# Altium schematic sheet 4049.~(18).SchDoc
size A4
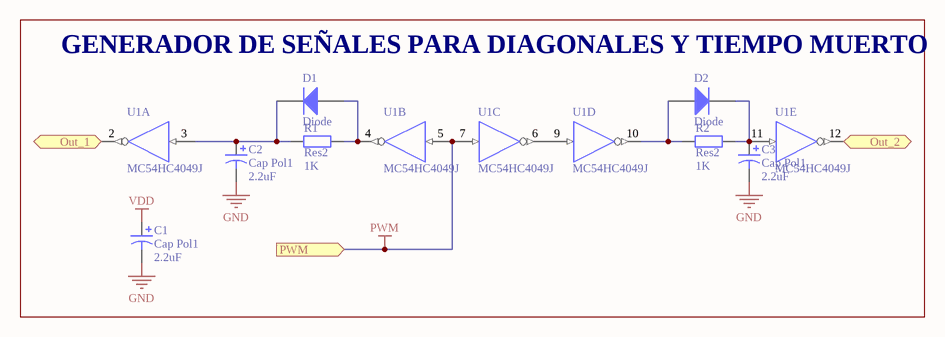
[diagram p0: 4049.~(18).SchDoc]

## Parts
C1  Cap Pol1  value 2.2uF  [CAPPR2.5-6.3X5]
C2  Cap Pol1  value 2.2uF  [CAPPR2.5-6.3X5]
C3  Cap Pol1  value 2.2uF  [CAPPR2.5-6.3X5]
D1  Diode  [DO-204AL]
D2  Diode  [DO-204AL]
R1  Res2  value 1K  [AXIAL-0.3]
R2  Res2  value 1K  [AXIAL-0.3]
U1  MC54HC4049J  [620-09]  (parts A,B,C,D,E of 6)

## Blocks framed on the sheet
GENERADOR DE SEÑALES PARA DIAGONALES Y TIEMPO MUERTO: C1-C3 D1 D2 R1 R2 U1

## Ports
Out_1 (out), Out_2 (out), PWM (in)

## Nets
GND: C1.2 C2.2 C3.2 U1.8(GND)
PWM: U1.5(A) U1.7(A) ; port PWM
VDD: C1.1 U1.1(VDD)
Out_1: U1.2(Y) ; port Out_1
Out_2: U1.12(Y) ; port Out_2
NetC2_1: C2.1 D1.2(K) R1.1 U1.3(A)
NetC3_1: C3.1 D2.2(K) R2.2 U1.11(A)
NetD1_1: D1.1(A) R1.2 U1.4(Y)
NetD2_1: D2.1(A) R2.1 U1.10(Y)
NetU1_6: U1.6(Y) U1.9(A)

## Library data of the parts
C1-C3 = Cap Pol1: Polarized Capacitor (Radial)
D1 D2 = Diode: Default Diode
R1 R2 = Res2: Resistor
U1 = MC54HC4049J: Hex Inverting Buffer/Logic-Level Down Converter; Note: Pins 13 & 16 are NC and not drawn.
